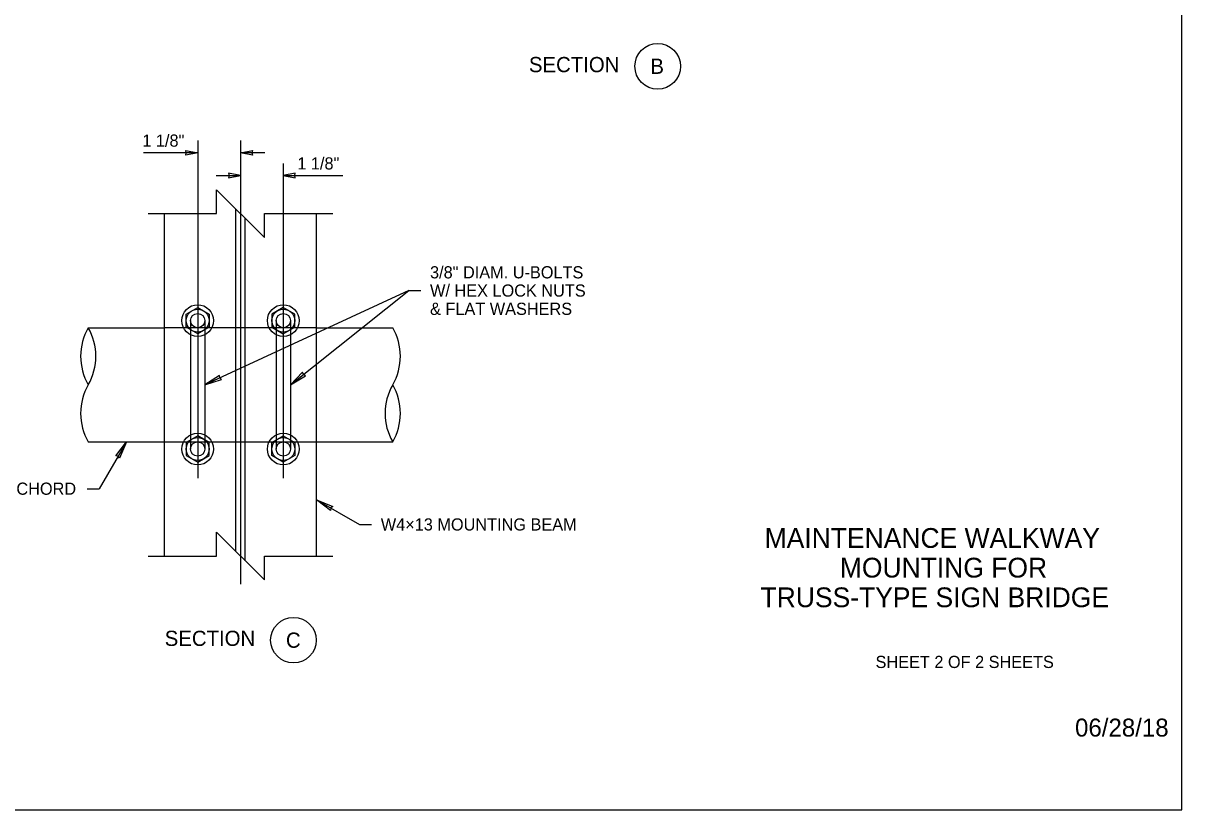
# Model space of a CAD drawing. Extents: x 99862 to 103151, y 100000 to 105076.
# Drawn here: x 101629 to 103151, y 103000 to 104033 of the extents above; entities that cross this region are included whole.
import ezdxf

# ---------------------------------------------------------------- set-up
doc = ezdxf.new("R2010")
doc.units = 0
for name, color, linetype in [('Level 1', 7, 'Continuous'), ('Level 15', 7, 'Continuous'), ('Level 20', 7, 'Continuous'), ('Level 36', 7, 'Continuous'), ('Level 4', 7, 'Continuous'), ('Level 6', 7, 'Continuous'), ('Level 62', 7, 'Continuous'), ('Level 9', 7, 'Continuous')]:
    doc.layers.add(name, color=color, linetype=linetype)

msp = doc.modelspace()

# ---------------------------------------------------------------- linework, layer by layer
at = {"layer": 'Level 1'}
msp.add_lwpolyline([(99862, 102999.5), (103151, 102999.5), (103151, 105075.5), (99862, 105075.5)], close=True, dxfattribs=at)
at = {"layer": 'Level 15'}
for p, q in [((101858, 103879.1), (101858, 103435.2)), ((101914.3, 103879.1), (101914.3, 103296.2)), ((101858, 103863.1), (101786.8, 103863.1)), ((101946.3, 103863.1), (101914.3, 103863.1)), ((101970.5, 103849.1), (101970.5, 103435.2)), ((101882.3, 103833.1), (101914.3, 103833.1)), ((101970.5, 103833.1), (102048.6, 103833.1)), ((102135.3, 103681.9), (102151.3, 103681.9)), ((101764.3, 103483.1), (101728.7, 103421.5)), ((101712.7, 103421.5), (101728.7, 103421.5)), ((102014.3, 103407.1), (102070.6, 103374.6)), ((102070.6, 103374.6), (102086.6, 103374.6))]:
    msp.add_line(p, q, dxfattribs=at)
for points in [[(101858, 103863.1), (101842.3, 103860), (101843, 103863.1), (101842.3, 103866.2)], [(101914.3, 103863.1), (101930, 103866.2), (101929.3, 103863.1), (101930, 103860)], [(101914.3, 103833.1), (101898.5, 103836.2), (101899.3, 103833.1), (101898.5, 103830)], [(101970.5, 103833.1), (101986.2, 103830), (101985.5, 103833.1), (101986.2, 103836.2)], [(101979.9, 103558.1), (101999.6, 103570), (101996.9, 103571.7), (101995.9, 103574.7)], [(101867.4, 103558.1), (101889.4, 103565), (101887.2, 103567.2), (101886.9, 103570.4)], [(101764.3, 103483.1), (101755.4, 103461.8), (101753.4, 103464.2), (101750.3, 103464.8)], [(102014.3, 103407.1), (102035.5, 103398.3), (102033.1, 103396.3), (102032.5, 103393.1)]]:
    msp.add_lwpolyline(points, close=True, dxfattribs=at)
for points in [[(101792.9, 103783.1), (101882.9, 103783.1), (101882.9, 103814.4), (101945.6, 103751.7), (101945.6, 103783.1), (102035.6, 103783.1)], [(101979.9, 103558.1), (102135.3, 103681.9), (101867.4, 103558.1)], [(101792.9, 103333.1), (101882.9, 103333.1), (101882.9, 103364.4), (101945.6, 103301.7), (101945.6, 103333.1), (102035.6, 103333.1)]]:
    msp.add_lwpolyline(points, dxfattribs=at)
for centre, start, end in [((101779.2, 103595.6), 150, 210), ((101649.3, 103595.6), 330, 30), ((102049.3, 103595.6), 330, 30), ((101779.2, 103520.6), 150, 210), ((102179.2, 103520.6), 150, 210), ((102049.3, 103520.6), 330, 30)]:
    msp.add_arc(centre, 75, start, end, dxfattribs=at)
at = {"layer": 'Level 36'}
for p, q in [((101848.6, 103642.5), (101848.6, 103473.7)), ((101867.4, 103642.5), (101867.4, 103473.7)), ((101961.1, 103642.5), (101961.1, 103473.7)), ((101979.9, 103642.5), (101979.9, 103473.7)), ((102014.3, 103633.1), (101814.3, 103633.1)), ((101814.3, 103483.1), (102014.3, 103483.1))]:
    msp.add_line(p, q, dxfattribs=at)
at = {"layer": 'Level 4'}
for p, q in [((101908, 103339.3), (101908, 103789.3)), ((101920.5, 103326.8), (101920.5, 103776.8))]:
    msp.add_line(p, q, dxfattribs=at)
for points in [[(101858, 103659.7), (101873, 103651.1), (101873, 103633.8), (101858, 103625.2), (101843, 103633.8), (101843, 103651.1)], [(101970.5, 103659.7), (101955.5, 103651.1), (101955.5, 103633.8), (101970.5, 103625.2), (101985.5, 103633.8), (101985.5, 103651.1)], [(101858, 103456.4), (101873, 103465.1), (101873, 103482.4), (101858, 103491), (101843, 103482.4), (101843, 103465.1)], [(101970.5, 103456.4), (101955.5, 103465.1), (101955.5, 103482.4), (101970.5, 103491), (101985.5, 103482.4), (101985.5, 103465.1)]]:
    msp.add_lwpolyline(points, close=True, dxfattribs=at)
at = {"layer": 'Level 6'}
for p, q in [((101814.3, 103333.1), (101814.3, 103783.1)), ((102014.3, 103333.1), (102014.3, 103783.1)), ((101714.3, 103633.1), (101814.3, 103633.1)), ((102014.3, 103633.1), (102114.3, 103633.1)), ((101714.3, 103483.1), (101814.3, 103483.1)), ((102014.3, 103483.1), (102114.3, 103483.1))]:
    msp.add_line(p, q, dxfattribs=at)
for centre, radius in [((101858, 103642.5), 20.9), ((101858, 103642.5), 15), ((101858, 103642.5), 9.38), ((101970.5, 103642.5), 20.9), ((101970.5, 103642.5), 15), ((101970.5, 103642.5), 9.38), ((101858, 103473.7), 20.9), ((101858, 103473.7), 15), ((101858, 103473.7), 9.38), ((101970.5, 103473.7), 20.9), ((101970.5, 103473.7), 15), ((101970.5, 103473.7), 9.38)]:
    msp.add_circle(centre, radius, dxfattribs=at)
at = {"layer": 'Level 9'}
for centre in [(102462.4, 103976.7), (101983.9, 103222.5)]:
    msp.add_circle(centre, 30, dxfattribs=at)

# ---------------------------------------------------------------- texts
at = {"layer": 'Level 15'}
msp.add_text('06/28/18', height=23.62, dxfattribs=at).set_placement((103010.7, 103095.8))
at = {"layer": 'Level 20'}
for s, height, p in [('SECTION', 20, (102293.2, 103969)), ('B', 20, (102452.8, 103966.8)), ('1 1/8"', 16, (101785.3, 103871.1)), ('1 1/8"', 16, (101988.9, 103841.1)), ('3/8" DIAM. U-BOLTS', 16, (102163.3, 103698)), ('W/ HEX LOCK NUTS', 16, (102163.3, 103674)), ('& FLAT WASHERS', 16, (102163.3, 103650)), ('TRUSS CHORD', 16, (101541.4, 103413.6)), ('W4×13 MOUNTING BEAM', 16, (102098.6, 103366.6)), ('SECTION', 20, (101814.7, 103214.9)), ('C', 20, (101974, 103212.5))]:
    msp.add_text(s, height=height, dxfattribs=at).set_placement(p)
at = {"layer": 'Level 62'}
for s, height, p in [('MAINTENANCE WALKWAY', 26, (102602.9, 103343.8)), ('MOUNTING FOR', 26, (102701.7, 103304.8)), ('TRUSS-TYPE SIGN BRIDGE', 26, (102597.5, 103265.8)), ('SHEET 2 OF 2 SHEETS', 16, (102748.6, 103185.9))]:
    msp.add_text(s, height=height, dxfattribs=at).set_placement(p)

doc.saveas('drawing.dxf')
